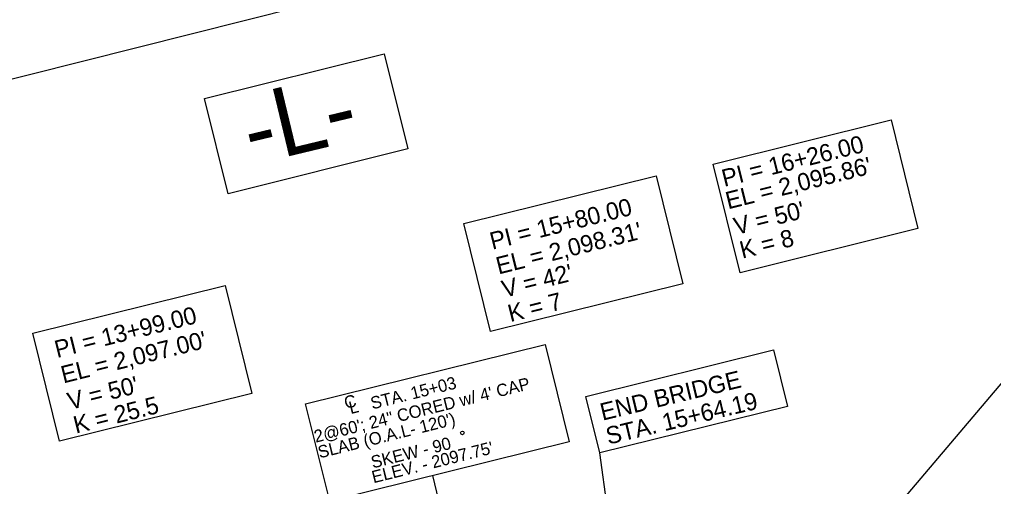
# Model space of a CAD drawing. Extents: x 1030663 to 1033857, y 654635 to 657099.
# Drawn here: x 1031298.2 to 1031692.3, y 656230.1 to 656419.1 of the extents above; entities that cross this region are included whole.
import ezdxf

# ---------------------------------------------------------------- set-up
doc = ezdxf.new("R2010")
doc.units = 0
for name, color, linetype in [('Default', 7, 'Continuous'), ('Prop Grid Mask', 7, 'Continuous'), ('Prop PFL Text', 7, 'Continuous'), ('Prop Vertical Profile Grade Label', 7, 'Continuous'), ('Prop VPI Label', 7, 'Continuous'), ('Sheet Layout Plan Border', 7, 'Continuous')]:
    doc.layers.add(name, color=color, linetype=linetype)

msp = doc.modelspace()

# ---------------------------------------------------------------- linework, layer by layer
at = {"layer": 'Default'}
msp.add_line((1031480.61, 656173.24), (1031465.38, 656234.47), dxfattribs=at)
at = {"layer": 'Prop Grid Mask'}
for points in [[(1031372.99, 656387.16), (1031445.72, 656405.3), (1031455.33, 656366.74), (1031382.61, 656348.6)], [(1031661.7, 656334.47), (1031589.71, 656316.62), (1031578.81, 656360.61), (1031650.8, 656378.45)], [(1031566.56, 656312.1), (1031488.81, 656292.83), (1031477.99, 656336.52), (1031555.73, 656355.79)], [(1031392.17, 656267.7), (1031314.42, 656248.43), (1031303.59, 656292.12), (1031381.34, 656311.39)], [(1031413.95, 656263.49), (1031510.89, 656287.51), (1031520.64, 656248.16), (1031423.7, 656224.15)], [(1031527.27, 656266.53), (1031603.26, 656285.36), (1031608.92, 656262.5), (1031532.93, 656243.67)]]:
    msp.add_lwpolyline(points, close=True, dxfattribs=at)
at = {"layer": 'Prop PFL Text'}
msp.add_circle((1031477.38, 656251.76), 0.729, dxfattribs=at)
at = {"layer": 'Prop Vertical Profile Grade Label'}
for p, q in [((1031629.16, 656193.64), (1031706.57, 656284.94)), ((1031541.32, 656182.67), (1031532.93, 656243.67))]:
    msp.add_line(p, q, dxfattribs=at)
at = {"layer": 'Sheet Layout Plan Border'}
msp.add_lwpolyline([(1030815.44, 656273.49), (1030662.78, 656790.18), (1030975.88, 656867.42), (1031909.35, 657099.34), (1031951.26, 656924.63), (1032228.73, 656630.06), (1031213.15, 656374.38)], close=True, dxfattribs=at)

# ---------------------------------------------------------------- texts
at = {"layer": 'Prop PFL Text'}
for s, p in [(' 2@60\'; 24" CORED w/ 4\' CAP', (1031416.25, 656247.33)), ('STA. 15+03', (1031440.92, 656261.24)), ('C', (1031430.23, 656261.45)), ('L', (1031432.19, 656259.35)), (" SLAB (O.A.L- 120')", (1031417.83, 656240.97)), ('SKEW - 90', (1031441.11, 656237.36)), ("ELEV. - 2097.75'", (1031441.43, 656231.36))]:
    msp.add_text(s, height=5, rotation=13.9999, dxfattribs=at).set_placement(p)
at = {"layer": 'Prop Vertical Profile Grade Label'}
for s, p in [('END BRIDGE', (1031534.07, 656256.7)), ('STA. 15+64.19', (1031536.4, 656246.98))]:
    msp.add_text(s, height=7, rotation=13.4999, dxfattribs=at).set_placement(p)
at = {"layer": 'Prop VPI Label'}
for s, height, rotation, p in [('-L-', 28, 13.4999, (1031392.17, 656360.15)), ('PI = 16+26.00', 7, 14, (1031583.3, 656351.35)), ("EL = 2,095.86'", 7, 14, (1031584.88, 656342.26)), ('PI = 15+80.00', 7, 14, (1031489.48, 656325.9)), ("V = 50'", 7, 14, (1031588.19, 656331.89)), ("EL = 2,098.31'", 7, 14, (1031491.98, 656315.89)), ('K = 8', 7, 14, (1031590.59, 656322.28)), ("V = 42'", 7, 14, (1031494.33, 656306.46)), ('K = 7', 7, 14, (1031496.78, 656296.62)), ('PI = 13+99.00', 7, 14, (1031313.38, 656282.07)), ("EL = 2,097.00'", 7, 14, (1031315.95, 656271.77)), ("V = 50'", 7, 14, (1031318.62, 656261.05)), ('K = 25.5', 7, 14, (1031321.02, 656251.44))]:
    msp.add_text(s, height=height, rotation=rotation, dxfattribs=at).set_placement(p)

doc.saveas('drawing.dxf')
